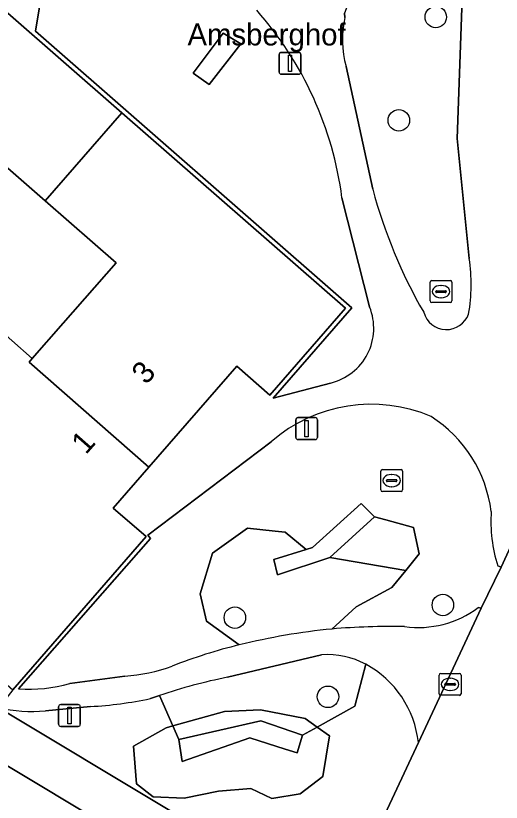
# Model space of a CAD drawing. Extents: x 160102 to 160934, y 382045 to 382923.
# Drawn here: x 160833.03 to 160855.17, y 382756.55 to 382792.39 of the extents above; entities that cross this region are included whole.
import ezdxf

# ---------------------------------------------------------------- set-up
doc = ezdxf.new("R2010")
doc.units = 0
for name, color, linetype in [('IMGEO_Boom', 7, 'Continuous'), ('IMGEO_Brandkraan', 7, 'Continuous'), ('IMGEO_Erf', 7, 'Continuous'), ('IMGEO_Groenvoorziening', 7, 'Continuous'), ('IMGEO_Haag', 7, 'Continuous'), ('IMGEO_Kolk', 7, 'Continuous'), ('IMGEO_Lichtmast', 7, 'Continuous'), ('IMGEO_Openbare_ruimte_label', 7, 'Continuous'), ('IMGEO_Pand', 7, 'Continuous'), ('IMGEO_Pand_nummerreeks', 7, 'Continuous'), ('IMGEO_Rijbaan_lokaal_open', 7, 'Continuous'), ('IMGEO_Rioolput', 7, 'Continuous'), ('IMGEO_Voetpad_open', 7, 'Continuous')]:
    doc.layers.add(name, color=color, linetype=linetype)

msp = doc.modelspace()

# ---------------------------------------------------------------- linework, layer by layer
at = {"layer": 'IMGEO_Boom'}
for centre in [(160852.181, 382792.326), (160850.497, 382787.618), (160852.504, 382765.534), (160843.022, 382764.958), (160847.267, 382761.351)]:
    msp.add_circle(centre, 0.489, dxfattribs=at)
at = {"layer": 'IMGEO_Brandkraan'}
for p, q in [((160849.745, 382771.703), (160850.597, 382771.703)), ((160849.67, 382770.777), (160849.67, 382771.629)), ((160850.158, 382771.483), (160850.183, 382771.483)), ((160850.671, 382771.629), (160850.671, 382770.777)), ((160849.929, 382771.197), (160849.929, 382771.209)), ((160850.367, 382771.16), (160849.969, 382771.16)), ((160849.972, 382771.246), (160850.37, 382771.246)), ((160850.413, 382771.209), (160850.413, 382771.197)), ((160850.597, 382770.703), (160849.745, 382770.703)), ((160850.181, 382770.923), (160850.156, 382770.923))]:
    msp.add_line(p, q, dxfattribs=at)
for points in [[(160849.745, 382771.703), (160850.597, 382771.703)], [(160849.67, 382770.777), (160849.67, 382771.629)], [(160850.671, 382771.629), (160850.671, 382770.777)], [(160850.597, 382770.703), (160849.745, 382770.703)]]:
    msp.add_lwpolyline(points, dxfattribs=at)
for centre, radius, start, end in [((160849.747, 382771.627), 0.0765, 91.552, 178.448), ((160849.747, 382771.627), 0.0765, 91.552, 178.448), ((160850.595, 382771.627), 0.0765, 1.552, 88.448), ((160850.595, 382771.627), 0.0765, 1.552, 88.448), ((160849.969, 382771.206), 0.0403, 85.8775, 175.7526), ((160849.966, 382771.196), 0.0366, 178.938, 274.7102), ((160850.37, 382771.203), 0.043, 264.8664, 352.4533), ((160850.374, 382771.208), 0.0386, 1.7309, 96.639), ((160849.747, 382770.779), 0.0765, 181.552, 268.448), ((160849.747, 382770.779), 0.0765, 181.552, 268.448), ((160850.595, 382770.779), 0.0765, 271.552, 358.448), ((160850.595, 382770.779), 0.0765, 271.552, 358.448)]:
    msp.add_arc(centre, radius, start, end, dxfattribs=at)
for centre, major_axis, ratio, start_param, end_param in [((160850.157, 382771.203), (-0.387, 0.002), 0.722429, 4.712389, 7.853982), ((160850.182, 382771.203), (-0.39, 0.002), 0.717154, 1.570796, 4.712389)]:
    msp.add_ellipse(centre, major_axis=major_axis, ratio=ratio, start_param=start_param, end_param=end_param, dxfattribs=at)
at = {"layer": 'IMGEO_Erf'}
msp.add_lwpolyline([(160826.464, 382781.024), (160830.835, 382777.186), (160831.906, 382778.41), (160833.788, 382776.764), (160835.201, 382778.379), (160837.607, 382781.129), (160834.37, 382783.95), (160831.325, 382786.604), (160828.818, 382783.726)], close=True, dxfattribs=at)
at = {"layer": 'IMGEO_Groenvoorziening'}
for points in [[(160853.705, 382781.324), (160853.157, 382786.784), (160853.365, 382792.729), (160852.387, 382793.551), (160851.065, 382799.698), (160851.324, 382802.631), (160849.48, 382796.37), (160848.016, 382792.502), (160848.036, 382792.303)], [(160834.312, 382794.594), (160834.211, 382793.359), (160833.928, 382791.677), (160848.357, 382779.075), (160844.771, 382774.96), (160847.383, 382775.65)], [(160848.09, 382790.074), (160849.305, 382784.488)], [(160849.164, 382779.115), (160847.905, 382784.087)], [(160844.683, 382772.977), (160839.052, 382768.719), (160839.183, 382768.563), (160833.159, 382761.712)], [(160841.729, 382764.802), (160841.442, 382766.038), (160842, 382767.891), (160843.603, 382769.035), (160844.864, 382768.899), (160845.315, 382768.85), (160846.279, 382768.07), (160846.554, 382768.156), (160848.784, 382770.158), (160849.389, 382769.558), (160849.902, 382769.415), (160851.165, 382769.064), (160851.431, 382767.867), (160850.818, 382767.113), (160850.185, 382766.335), (160848.553, 382765.446), (160847.448, 382764.44)], [(160847.345, 382767.702), (160844.96, 382766.905), (160844.794, 382767.603), (160846.279, 382768.07), (160845.315, 382768.85), (160844.864, 382768.899), (160843.603, 382769.035), (160842, 382767.891), (160841.442, 382766.038), (160841.729, 382764.802), (160843.225, 382763.715)], [(160847.448, 382764.44), (160848.553, 382765.446), (160850.185, 382766.335), (160850.818, 382767.113), (160847.345, 382767.702)], [(160854.112, 382765.416), (160854.243, 382765.384), (160855.156, 382767.252), (160855.005, 382767.319)], [(160843.225, 382763.715), (160841.729, 382764.802)], [(160846.973, 382763.267), (160842.681, 382762.243)], [(160848.992, 382762.832), (160848.494, 382760.92), (160846.776, 382759.973), (160847.339, 382759.569), (160847.037, 382757.717), (160845.999, 382756.926), (160844.715, 382756.721), (160843.747, 382757.168), (160842.277, 382757.056), (160840.713, 382756.74), (160839.295, 382756.787), (160838.536, 382757.391), (160838.406, 382759.104), (160839.894, 382759.942)], [(160839.589, 382761.416), (160840.195, 382760.026), (160842.556, 382760.686), (160844.194, 382760.761), (160846.222, 382760.37), (160846.776, 382759.973), (160848.494, 382760.92), (160848.992, 382762.832)], [(160835.505, 382761.951), (160838.011, 382762.298)], [(160839.894, 382759.942), (160840.195, 382760.026), (160839.589, 382761.416), (160839.169, 382761.268)], [(160836.444, 382760.908), (160834.388, 382760.716)], [(160832.254, 382760.853), (160847.78, 382751.534), (160851.387, 382759.264)], [(160846.897, 382749.655), (160832.394, 382758.36), (160819.232, 382742.583)]]:
    msp.add_lwpolyline(points, dxfattribs=at)
for points in [[(160843.3, 382791.098), (160842.491, 382791.584), (160841.116, 382789.769), (160841.845, 382789.245)], [(160841.845, 382789.245), (160841.116, 382789.769), (160842.491, 382791.584), (160843.3, 382791.098)], [(160848.784, 382770.158), (160846.554, 382768.156), (160846.279, 382768.07), (160844.794, 382767.603), (160844.96, 382766.905), (160847.345, 382767.702), (160849.389, 382769.558)], [(160851.165, 382769.064), (160849.902, 382769.415), (160849.389, 382769.558), (160847.345, 382767.702), (160850.818, 382767.113), (160851.431, 382767.867)], [(160840.467, 382759.401), (160844.206, 382760.258), (160846.103, 382759.602), (160846.776, 382759.973), (160846.222, 382760.37), (160844.194, 382760.761), (160842.556, 382760.686), (160840.195, 382760.026)], [(160845.862, 382758.794), (160846.103, 382759.602), (160844.206, 382760.258), (160840.467, 382759.401), (160840.617, 382758.411), (160843.705, 382759.481), (160845.321, 382758.966)], [(160840.195, 382760.026), (160839.894, 382759.942), (160838.406, 382759.104), (160838.536, 382757.391), (160839.295, 382756.787), (160840.713, 382756.74), (160842.277, 382757.056), (160843.747, 382757.168), (160844.715, 382756.721), (160845.999, 382756.926), (160847.037, 382757.717), (160847.339, 382759.569), (160846.776, 382759.973), (160846.103, 382759.602), (160845.862, 382758.794), (160845.321, 382758.966), (160843.705, 382759.481), (160840.617, 382758.411), (160840.467, 382759.401)]]:
    msp.add_lwpolyline(points, close=True, dxfattribs=at)
for centre, radius, start, end in [((160831.959, 382781.996), 16.083, 7.4715, 41.4355), ((160852.528, 382791.297), 4.603, 167.3715, 195.4041), ((160871.849, 382790.537), 23.342, 195.0198, 209.9865), ((160845.741, 382780.141), 8.052, 350.3714, 8.451), ((160846.784, 382778.148), 2.569, 283.4798, 22.1141), ((160852.668, 382779.162), 1.076, 195.7066, 339.985), ((160849.24, 382767.744), 6.939, 66.7835, 131.0487), ((160848.658, 382768.993), 6.107, 7.5743, 57.1036), ((160861.225, 382769.311), 6.531, 175.7229, 197.7584), ((160851.38, 382769.07), 4.562, 262.2082, 306.7799), ((160850.14, 382733.306), 31.251, 88.86, 94.9422), ((160850.329, 382734.999), 29.582, 95.5883, 103.8947), ((160848.496, 382741.655), 22.681, 103.4371, 111.5459), ((160847.249, 382759.644), 3.633, 61.3284, 94.3542), ((160837.503, 382770.066), 7.785, 273.7402, 290.0023), ((160846.786, 382758.764), 4.628, 6.2077, 61.5348), ((160847.847, 382736.733), 26.028, 101.449, 108.4992), ((160833.611, 382768.911), 7.213, 266.4093, 285.2246), ((160835.404, 382779.274), 18.395, 273.2411, 281.8105), ((160833.756, 382767.562), 6.875, 257.3799, 275.2736)]:
    msp.add_arc(centre, radius, start, end, dxfattribs=at)
at = {"layer": 'IMGEO_Haag'}
for points in [[(160843.3, 382791.098), (160842.491, 382791.584), (160841.116, 382789.769), (160841.845, 382789.245)], [(160848.784, 382770.158), (160846.554, 382768.156), (160846.279, 382768.07), (160844.794, 382767.603), (160844.96, 382766.905), (160847.345, 382767.702), (160849.389, 382769.558)], [(160845.862, 382758.794), (160846.103, 382759.602), (160844.206, 382760.258), (160840.467, 382759.401), (160840.617, 382758.411), (160843.705, 382759.481), (160845.321, 382758.966)]]:
    msp.add_lwpolyline(points, close=True, dxfattribs=at)
at = {"layer": 'IMGEO_Kolk'}
for p, q in [((160852.332, 382761.493), (160852.332, 382762.345)), ((160852.407, 382762.419), (160853.259, 382762.419)), ((160853.333, 382762.345), (160853.333, 382761.493)), ((160852.82, 382762.199), (160852.845, 382762.199)), ((160852.591, 382761.913), (160852.591, 382761.925)), ((160853.029, 382761.876), (160852.631, 382761.876)), ((160852.634, 382761.962), (160853.032, 382761.962)), ((160852.843, 382761.639), (160852.818, 382761.639)), ((160853.075, 382761.925), (160853.075, 382761.913)), ((160853.259, 382761.419), (160852.407, 382761.419))]:
    msp.add_line(p, q, dxfattribs=at)
for points in [[(160852.332, 382761.493), (160852.332, 382762.345)], [(160852.407, 382762.419), (160853.259, 382762.419)], [(160853.333, 382762.345), (160853.333, 382761.493)], [(160853.259, 382761.419), (160852.407, 382761.419)]]:
    msp.add_lwpolyline(points, dxfattribs=at)
for centre, radius, start, end in [((160852.409, 382762.343), 0.0765, 91.552, 178.448), ((160852.409, 382762.343), 0.0765, 91.552, 178.448), ((160853.257, 382762.343), 0.0765, 1.552, 88.448), ((160853.257, 382762.343), 0.0765, 1.552, 88.448), ((160852.631, 382761.922), 0.0403, 85.8775, 175.7526), ((160852.628, 382761.912), 0.0366, 178.938, 274.7102), ((160853.032, 382761.919), 0.043, 264.8664, 352.4533), ((160853.036, 382761.924), 0.0386, 1.7309, 96.639), ((160852.409, 382761.495), 0.0765, 181.552, 268.448), ((160852.409, 382761.495), 0.0765, 181.552, 268.448), ((160853.257, 382761.495), 0.0765, 271.552, 358.448), ((160853.257, 382761.495), 0.0765, 271.552, 358.448)]:
    msp.add_arc(centre, radius, start, end, dxfattribs=at)
for centre, major_axis, ratio, start_param, end_param in [((160852.819, 382761.919), (-0.387, 0.002), 0.722429, 4.712389, 7.853982), ((160852.844, 382761.919), (-0.39, 0.002), 0.717154, 1.570796, 4.712389)]:
    msp.add_ellipse(centre, major_axis=major_axis, ratio=ratio, start_param=start_param, end_param=end_param, dxfattribs=at)
at = {"layer": 'IMGEO_Lichtmast'}
for p, q in [((160845.14, 382790.717), (160845.93, 382790.717)), ((160845.93, 382790.717), (160845.14, 382790.717)), ((160845.04, 382789.817), (160845.04, 382790.617)), ((160845.04, 382790.617), (160845.04, 382789.817)), ((160846.03, 382790.617), (160846.03, 382789.817)), ((160846.03, 382789.817), (160846.03, 382790.617)), ((160845.93, 382789.717), (160845.14, 382789.717)), ((160845.14, 382789.717), (160845.93, 382789.717)), ((160845.797, 382773.171), (160845.797, 382773.971)), ((160845.797, 382773.971), (160845.797, 382773.171)), ((160845.897, 382774.071), (160846.687, 382774.071)), ((160846.687, 382774.071), (160845.897, 382774.071)), ((160846.787, 382773.971), (160846.787, 382773.171)), ((160846.787, 382773.171), (160846.787, 382773.971)), ((160846.687, 382773.071), (160845.897, 382773.071)), ((160845.897, 382773.071), (160846.687, 382773.071)), ((160834.987, 382760.101), (160834.987, 382760.901)), ((160834.987, 382760.901), (160834.987, 382760.101)), ((160835.087, 382761.001), (160835.877, 382761.001)), ((160835.877, 382761.001), (160835.087, 382761.001)), ((160835.977, 382760.901), (160835.977, 382760.101)), ((160835.977, 382760.101), (160835.977, 382760.901)), ((160835.877, 382760.001), (160835.087, 382760.001)), ((160835.087, 382760.001), (160835.877, 382760.001))]:
    msp.add_line(p, q, dxfattribs=at)
for points in [[(160845.46, 382790.592), (160845.61, 382790.592), (160845.61, 382789.842), (160845.46, 382789.842), (160845.46, 382790.592)], [(160846.217, 382773.946), (160846.367, 382773.946), (160846.367, 382773.196), (160846.217, 382773.196), (160846.217, 382773.946)], [(160835.407, 382760.876), (160835.557, 382760.876), (160835.557, 382760.126), (160835.407, 382760.126), (160835.407, 382760.876)]]:
    msp.add_lwpolyline(points, dxfattribs=at)
for centre, start, end in [((160845.14, 382790.617), 90, 180), ((160845.14, 382790.617), 90, 180), ((160845.93, 382790.617), 0, 90), ((160845.93, 382790.617), 360, 90), ((160845.14, 382789.817), 180, 270), ((160845.14, 382789.817), 180, 270), ((160845.93, 382789.817), 270, 0), ((160845.93, 382789.817), 270, 0), ((160845.897, 382773.971), 90, 180), ((160845.897, 382773.971), 90, 180), ((160846.687, 382773.971), 0, 90), ((160846.687, 382773.971), 360, 90), ((160845.897, 382773.171), 180, 270), ((160845.897, 382773.171), 180, 270), ((160846.687, 382773.171), 270, 0), ((160846.687, 382773.171), 270, 0), ((160835.087, 382760.901), 90, 180), ((160835.087, 382760.901), 90, 180), ((160835.877, 382760.901), 0, 90), ((160835.877, 382760.901), 360, 90), ((160835.087, 382760.101), 180, 270), ((160835.087, 382760.101), 180, 270), ((160835.877, 382760.101), 270, 0), ((160835.877, 382760.101), 270, 0)]:
    msp.add_arc(centre, 0.1, start, end, dxfattribs=at)
at = {"layer": 'IMGEO_Pand'}
for points in [[(160837.876, 382787.962), (160830.12, 382794.741), (160821.733, 382785.145), (160826.464, 382781.024), (160828.818, 382783.726), (160831.325, 382786.604), (160834.37, 382783.95)], [(160837.876, 382787.962), (160834.37, 382783.95), (160837.607, 382781.129), (160835.201, 382778.379), (160833.788, 382776.764), (160833.64, 382776.596), (160839.104, 382771.818), (160843.112, 382776.416), (160844.623, 382775.099), (160848.068, 382779.054)], [(160839.104, 382771.818), (160833.64, 382776.596), (160833.788, 382776.764), (160831.906, 382778.41), (160830.835, 382777.186), (160826.688, 382772.445), (160831.599, 382768.149), (160828.956, 382765.131), (160832.906, 382761.671), (160838.975, 382768.654), (160837.479, 382769.954)]]:
    msp.add_lwpolyline(points, close=True, dxfattribs=at)
at = {"layer": 'IMGEO_Rijbaan_lokaal_open'}
msp.add_lwpolyline([(160848.871, 382738.983), (160847.977, 382739.405), (160849.284, 382742.212), (160857.045, 382758.717), (160858.349, 382761.529), (160864.175, 382773.992), (160870.234, 382786.936), (160865.965, 382790.473), (160865.463, 382789.419), (160862.922, 382784.019), (160860.656, 382779.204), (160859.334, 382776.335), (160855.156, 382767.252), (160854.243, 382765.384), (160851.387, 382759.264), (160847.78, 382751.534), (160846.897, 382749.655), (160841.095, 382737.186), (160840.341, 382735.558), (160832.435, 382718.448), (160829.713, 382712.474)], dxfattribs=at)
at = {"layer": 'IMGEO_Rioolput'}
for p, q in [((160851.994, 382780.314), (160852.846, 382780.314)), ((160851.919, 382779.388), (160851.919, 382780.24)), ((160852.407, 382780.094), (160852.432, 382780.094)), ((160852.92, 382780.24), (160852.92, 382779.388)), ((160852.178, 382779.808), (160852.178, 382779.82)), ((160852.616, 382779.771), (160852.218, 382779.771)), ((160852.221, 382779.857), (160852.619, 382779.857)), ((160852.43, 382779.534), (160852.405, 382779.534)), ((160852.662, 382779.82), (160852.662, 382779.808)), ((160852.846, 382779.314), (160851.994, 382779.314))]:
    msp.add_line(p, q, dxfattribs=at)
for points in [[(160851.994, 382780.314), (160852.846, 382780.314)], [(160851.919, 382779.388), (160851.919, 382780.24)], [(160852.92, 382780.24), (160852.92, 382779.388)], [(160852.846, 382779.314), (160851.994, 382779.314)]]:
    msp.add_lwpolyline(points, dxfattribs=at)
for centre, radius, start, end in [((160851.996, 382780.238), 0.0765, 91.552, 178.448), ((160851.996, 382780.238), 0.0765, 91.552, 178.448), ((160852.844, 382780.238), 0.0765, 1.552, 88.448), ((160852.844, 382780.238), 0.0765, 1.552, 88.448), ((160852.218, 382779.817), 0.0403, 85.8775, 175.7526), ((160852.215, 382779.807), 0.0366, 178.938, 274.7102), ((160852.619, 382779.814), 0.043, 264.8664, 352.4533), ((160852.623, 382779.819), 0.0386, 1.7309, 96.639), ((160851.996, 382779.39), 0.0765, 181.552, 268.448), ((160851.996, 382779.39), 0.0765, 181.552, 268.448), ((160852.844, 382779.39), 0.0765, 271.552, 358.448), ((160852.844, 382779.39), 0.0765, 271.552, 358.448)]:
    msp.add_arc(centre, radius, start, end, dxfattribs=at)
for centre, major_axis, ratio, start_param, end_param in [((160852.406, 382779.814), (-0.387, 0.002), 0.722429, 4.712389, 7.853982), ((160852.431, 382779.814), (-0.39, 0.002), 0.717154, 1.570796, 4.712389)]:
    msp.add_ellipse(centre, major_axis=major_axis, ratio=ratio, start_param=start_param, end_param=end_param, dxfattribs=at)
at = {"layer": 'IMGEO_Voetpad_open'}
for points in [[(160830.39, 382817.018), (160830.912, 382819.594), (160825.02, 382824.486), (160824.697, 382824.086), (160822.575, 382821.627), (160828.523, 382816.423), (160826.573, 382811.372), (160824.713, 382806.555), (160822.79, 382801.577), (160822.666, 382801.256), (160830.12, 382794.741), (160837.876, 382787.962), (160848.068, 382779.054), (160844.623, 382775.099), (160843.112, 382776.416), (160839.104, 382771.818), (160837.479, 382769.954), (160838.975, 382768.654), (160832.906, 382761.671), (160832.254, 382760.853)], [(160847.383, 382775.65), (160844.771, 382774.96), (160848.357, 382779.075), (160833.928, 382791.677), (160834.211, 382793.359), (160834.312, 382794.594)], [(160853.38, 382793.168), (160853.365, 382792.729), (160853.157, 382786.784), (160853.705, 382781.324)], [(160848.036, 382792.303), (160848.016, 382792.502)], [(160849.305, 382784.488), (160848.09, 382790.074)], [(160847.905, 382784.087), (160849.164, 382779.115)], [(160855.005, 382767.319), (160855.156, 382767.252), (160859.334, 382776.335), (160858.418, 382776.997), (160857.366, 382777.995)], [(160833.159, 382761.712), (160839.183, 382768.563), (160839.052, 382768.719), (160844.683, 382772.977)], [(160851.387, 382759.264), (160854.243, 382765.384), (160854.112, 382765.416)], [(160842.681, 382762.243), (160846.973, 382763.267)], [(160838.011, 382762.298), (160835.505, 382761.951)], [(160839.169, 382761.268), (160839.589, 382761.416)], [(160834.388, 382760.716), (160836.444, 382760.908)]]:
    msp.add_lwpolyline(points, dxfattribs=at)
msp.add_lwpolyline([(160830.838, 382759.299), (160832.394, 382758.36), (160846.897, 382749.655), (160847.78, 382751.534), (160832.254, 382760.853)], close=True, dxfattribs=at)
for centre, radius, start, end in [((160831.959, 382781.996), 16.083, 7.4715, 41.4355), ((160852.528, 382791.297), 4.603, 167.3715, 195.4041), ((160871.849, 382790.537), 23.342, 195.0198, 209.9865), ((160845.741, 382780.141), 8.052, 350.3714, 8.451), ((160846.784, 382778.148), 2.569, 283.4798, 22.1141), ((160852.668, 382779.162), 1.076, 195.7066, 339.985), ((160849.24, 382767.744), 6.939, 66.7835, 131.0487), ((160848.658, 382768.993), 6.107, 7.5743, 57.1036), ((160861.225, 382769.311), 6.531, 175.7229, 197.7584), ((160851.38, 382769.07), 4.562, 262.2082, 306.7799), ((160850.14, 382733.306), 31.251, 88.86, 94.9422), ((160850.329, 382734.999), 29.582, 95.5883, 103.8947), ((160848.496, 382741.655), 22.681, 103.4371, 111.5459), ((160847.249, 382759.644), 3.633, 61.3284, 94.3542), ((160837.503, 382770.066), 7.785, 273.7402, 290.0023), ((160846.786, 382758.764), 4.628, 6.2077, 61.5348), ((160847.847, 382736.733), 26.028, 101.449, 108.4992), ((160833.611, 382768.911), 7.213, 266.4093, 285.2246), ((160835.404, 382779.274), 18.395, 273.2411, 281.8105), ((160833.756, 382767.562), 6.875, 257.3799, 275.2736)]:
    msp.add_arc(centre, radius, start, end, dxfattribs=at)

# ---------------------------------------------------------------- texts
at = {"layer": 'IMGEO_Openbare_ruimte_label'}
msp.add_text('Amsberghof', height=1, dxfattribs=at).set_placement((160840.862, 382791.032))
at = {"layer": 'IMGEO_Pand_nummerreeks'}
for s, rotation, p in [('3', 49.0856, (160838.983, 382775.536)), ('1', 48.6755, (160836.232, 382772.355))]:
    msp.add_text(s, height=1, rotation=rotation, dxfattribs=at).set_placement(p)

doc.saveas('drawing.dxf')
